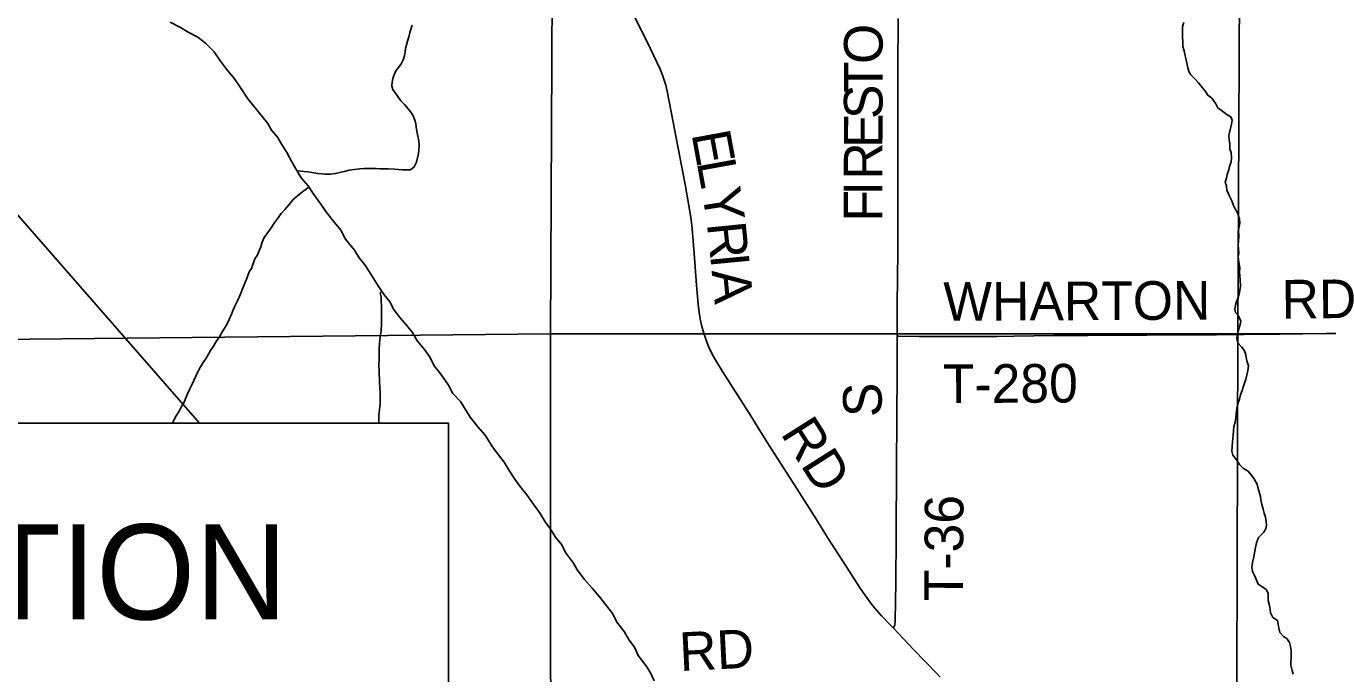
# Model space of a CAD drawing. Extents: x 0 to 34, y 0 to 22.
# Drawn here: x 4.701 to 6.615, y 18.929 to 19.882 of the extents above; entities that cross this region are included whole.
import ezdxf

# ---------------------------------------------------------------- set-up
doc = ezdxf.new("R2010")
doc.units = 0
for name, color, linetype in [('GM_X_County_Road', 7, 'Continuous'), ('GM_X_County_Road_Text', 7, 'Continuous'), ('GM_X_Minor_River', 7, 'Continuous'), ('GM_X_Rail_Line', 7, 'Continuous'), ('GM_X_Section', 7, 'Continuous'), ('GM_X_Township_Road', 7, 'Continuous'), ('GM_X_Township_Road_Text', 7, 'Continuous'), ('SH_Text', 7, 'Continuous')]:
    doc.layers.add(name, color=color, linetype=linetype)

msp = doc.modelspace()

# ---------------------------------------------------------------- linework, layer by layer
at = {"layer": 'GM_X_County_Road'}
for points in [[(5.976, 18.9964), (5.9715, 19.0011), (5.9588, 19.0146), (5.9483, 19.0263), (5.9426, 19.0337), (5.9351, 19.0437), (5.9263, 19.0565), (5.9061, 19.0879), (5.8794, 19.1298), (5.8629, 19.1562), (5.8346, 19.2008), (5.8113, 19.2375), (5.7944, 19.2636), (5.7812, 19.2847), (5.7663, 19.3084), (5.7247, 19.3739), (5.7164, 19.3873), (5.7103, 19.3982), (5.7049, 19.4093), (5.7013, 19.4182), (5.6973, 19.4299), (5.694, 19.4419), (5.6919, 19.451), (5.6905, 19.4603), (5.6889, 19.4727), (5.6866, 19.5006), (5.6831, 19.547), (5.6801, 19.584), (5.6788, 19.5965), (5.676, 19.6149), (5.6699, 19.6485), (5.6494, 19.7553), (5.6434, 19.7858), (5.6414, 19.7948), (5.6388, 19.8035), (5.6365, 19.8095), (5.633, 19.818), (5.6186, 19.849), (5.605, 19.8769), (5.5837, 19.9184)], [(6.0449, 18.9245), (6.0402, 18.9292), (6.0056, 18.9649), (5.976, 18.9964)]]:
    msp.add_lwpolyline(points, dxfattribs=at)
at = {"layer": 'GM_X_Minor_River'}
for points in [[(4.9132, 19.8872), (4.928, 19.8793), (4.9394, 19.8728), (4.9538, 19.8653), (4.9648, 19.8566), (4.9778, 19.8437), (4.9869, 19.8301), (4.9957, 19.8184), (5.0075, 19.804), (5.017, 19.7904), (5.0273, 19.7748), (5.0379, 19.7616), (5.0482, 19.7487), (5.0566, 19.7385), (5.0619, 19.7283), (5.0707, 19.718), (5.0771, 19.7074), (5.0844, 19.6957), (5.0916, 19.682), (5.0977, 19.6718), (5.1057, 19.6586), (5.116, 19.6468), (5.124, 19.634), (5.1343, 19.6199), (5.1434, 19.6071), (5.1545, 19.5927), (5.164, 19.5817), (5.1709, 19.5681), (5.1838, 19.5522), (5.1907, 19.5408), (5.199, 19.5306), (5.2089, 19.5154), (5.2185, 19.4999), (5.2276, 19.4863), (5.2364, 19.4757), (5.2413, 19.4654), (5.2509, 19.4526), (5.2604, 19.442), (5.2687, 19.4314), (5.2764, 19.4185), (5.287, 19.406), (5.295, 19.3943), (5.3011, 19.3818), (5.311, 19.3696), (5.3221, 19.3537), (5.3286, 19.3412), (5.3396, 19.3295), (5.3537, 19.3064), (5.3651, 19.2924), (5.3761, 19.2799), (5.386, 19.2644), (5.3937, 19.2534), (5.4039, 19.2405), (5.412, 19.2265), (5.4184, 19.2167), (5.4268, 19.2049), (5.4371, 19.1924), (5.4458, 19.1807), (5.4569, 19.1648), (5.4641, 19.1527), (5.4721, 19.1421), (5.4794, 19.1299), (5.4885, 19.119), (5.4939, 19.1076), (5.506, 19.0921), (5.5114, 19.0822), (5.522, 19.0678), (5.5334, 19.055), (5.5445, 19.0417), (5.5548, 19.0285), (5.5635, 19.0175), (5.5696, 19.005), (5.5803, 18.9914), (5.5875, 18.9789), (5.5955, 18.9682), (5.6009, 18.9561), (5.6134, 18.9395), (5.6195, 18.9296), (5.6245, 18.919)], [(6.4439, 19.7757), (6.4382, 19.7799), (6.4348, 19.7852), (6.4283, 19.7932), (6.4244, 19.7982), (6.4195, 19.8035), (6.4133, 19.81), (6.4103, 19.8149), (6.4087, 19.8203), (6.4072, 19.8275), (6.406, 19.8336), (6.4045, 19.8404), (6.4033, 19.8454), (6.4014, 19.8514), (6.4014, 19.8568), (6.401, 19.867), (6.4009, 19.8811), (6.4028, 19.8868)], [(5.0997, 19.6685), (5.1153, 19.6674), (5.124, 19.6659), (5.1298, 19.6648), (5.1401, 19.664), (5.1485, 19.6636), (5.1561, 19.6648), (5.1641, 19.667), (5.1691, 19.6678), (5.1763, 19.6697), (5.1836, 19.6708), (5.1916, 19.6716), (5.1981, 19.6723), (5.2076, 19.6723), (5.216, 19.672), (5.221, 19.6719), (5.2282, 19.6716), (5.2336, 19.6716), (5.2431, 19.6712), (5.2481, 19.6708), (5.2542, 19.6704), (5.2664, 19.6704), (5.2717, 19.6746), (5.2751, 19.6814), (5.2766, 19.6879), (5.2778, 19.694), (5.2785, 19.6993), (5.2789, 19.7061), (5.2785, 19.713), (5.2769, 19.7198), (5.2754, 19.7271), (5.2746, 19.7331), (5.2739, 19.7381), (5.2727, 19.7434), (5.27, 19.7495), (5.2666, 19.7548), (5.2627, 19.7601), (5.2574, 19.7662), (5.252, 19.7719), (5.2478, 19.778), (5.244, 19.783), (5.2401, 19.7883), (5.2386, 19.7936), (5.2394, 19.7989), (5.2405, 19.8043), (5.2424, 19.81), (5.2447, 19.8157), (5.2485, 19.8206), (5.2526, 19.8263), (5.2553, 19.832), (5.2572, 19.8385), (5.2583, 19.8438), (5.2587, 19.8491), (5.2602, 19.8541), (5.2617, 19.8594), (5.2636, 19.8659), (5.2651, 19.8723), (5.2689, 19.883)], [(6.5244, 19.1479), (6.524, 19.1528), (6.5229, 19.1593), (6.521, 19.1654), (6.5194, 19.1711), (6.5175, 19.1783), (6.5163, 19.1848), (6.5156, 19.1901), (6.5136, 19.1969), (6.5117, 19.203), (6.5106, 19.208), (6.506, 19.2163), (6.5017, 19.222), (6.4975, 19.2274), (6.4907, 19.2312), (6.4849, 19.2369), (6.4803, 19.2437), (6.475, 19.2506), (6.4734, 19.2567), (6.4738, 19.2635), (6.4745, 19.2703), (6.4753, 19.2802), (6.476, 19.2867), (6.4764, 19.2924), (6.4787, 19.3011), (6.4794, 19.3065), (6.4805, 19.3164), (6.4813, 19.3221), (6.4828, 19.3274), (6.4847, 19.3331), (6.4862, 19.3392), (6.4885, 19.3456), (6.49, 19.3506), (6.4923, 19.3567), (6.4942, 19.3624), (6.4957, 19.3684), (6.4972, 19.3753), (6.4979, 19.3818), (6.4956, 19.3894), (6.4948, 19.3947), (6.4937, 19.4), (6.4918, 19.405), (6.4876, 19.4099), (6.4822, 19.416), (6.481, 19.4221), (6.4822, 19.4316), (6.486, 19.443), (6.4867, 19.4479), (6.4833, 19.4555), (6.4787, 19.4605), (6.4779, 19.4654), (6.479, 19.4711), (6.4805, 19.4768), (6.4828, 19.4825), (6.4843, 19.4879), (6.4851, 19.4928), (6.4862, 19.4993), (6.4858, 19.5084), (6.4854, 19.5141), (6.485, 19.5206), (6.4854, 19.5259), (6.4842, 19.532), (6.4834, 19.5373), (6.483, 19.5426), (6.4838, 19.5476), (6.4834, 19.5536), (6.4826, 19.5601), (6.4834, 19.565), (6.4837, 19.5727), (6.4833, 19.581), (6.4841, 19.5871), (6.4852, 19.5924), (6.4848, 19.5977), (6.4817, 19.6069), (6.4783, 19.613), (6.476, 19.6179), (6.4737, 19.6244), (6.4699, 19.6316), (6.466, 19.6404), (6.4656, 19.6468), (6.4637, 19.6521), (6.4656, 19.6582), (6.4667, 19.6632), (6.469, 19.6704), (6.4701, 19.6753), (6.4724, 19.6818), (6.4732, 19.6879), (6.4724, 19.6955), (6.4708, 19.7004), (6.4704, 19.7084), (6.4697, 19.7149), (6.4693, 19.7206), (6.4708, 19.727), (6.473, 19.7373), (6.4738, 19.743), (6.4719, 19.748), (6.4661, 19.7518), (6.4581, 19.7575), (6.4531, 19.7613), (6.4501, 19.7674), (6.4439, 19.7757)], [(5.1171, 19.645), (5.1092, 19.6393), (5.1005, 19.6325), (5.0932, 19.626), (5.0879, 19.6192), (5.0814, 19.6119), (5.0761, 19.6059), (5.07, 19.5979), (5.0658, 19.5918), (5.0624, 19.5865), (5.059, 19.5815), (5.0552, 19.5762), (5.051, 19.5709), (5.048, 19.5641), (5.0461, 19.5568), (5.0407, 19.5443), (5.0373, 19.5393), (5.0324, 19.5253), (5.029, 19.52), (5.0259, 19.512), (5.0229, 19.5036), (5.0191, 19.4952), (5.0157, 19.4865), (5.0123, 19.4785), (5.0092, 19.4717), (5.0062, 19.4652), (5.0032, 19.458), (4.9998, 19.45), (4.9956, 19.442), (4.9906, 19.4337), (4.9853, 19.4249), (4.9808, 19.4177), (4.9766, 19.4108), (4.9724, 19.4044), (4.9694, 19.3994), (4.9659, 19.3934), (4.9617, 19.3869), (4.9572, 19.3797), (4.953, 19.3721), (4.9454, 19.3553), (4.9412, 19.3474), (4.9382, 19.3409), (4.9348, 19.3325), (4.9329, 19.3276), (4.9298, 19.3223), (4.926, 19.3154), (4.9219, 19.3086), (4.9184, 19.3021), (4.9162, 19.2976)], [(5.224, 19.4917), (5.2218, 19.4894), (5.2229, 19.4833), (5.2233, 19.4776), (5.2237, 19.4696), (5.2238, 19.4491), (5.2234, 19.4438), (5.2231, 19.4335), (5.2219, 19.4271), (5.2212, 19.4206), (5.2208, 19.4141), (5.2204, 19.4073), (5.2201, 19.3997), (5.2201, 19.3921), (5.2197, 19.3833), (5.2201, 19.3742), (5.2209, 19.3582), (5.2213, 19.3506), (5.2217, 19.3423), (5.2218, 19.3343), (5.2214, 19.3263), (5.2207, 19.3175), (5.2199, 19.3096), (5.2199, 19.3016), (5.2197, 19.2976)], [(6.5639, 18.9288), (6.562, 18.9341), (6.5604, 18.9417), (6.5604, 18.9467), (6.5608, 18.9524), (6.5608, 18.9573), (6.5608, 18.9634), (6.56, 18.9695), (6.5584, 18.9752), (6.5542, 18.9813), (6.5493, 18.984), (6.5443, 18.9901), (6.5424, 18.9961), (6.5416, 19.0022), (6.5408, 19.0075), (6.5339, 19.0121), (6.5305, 19.019), (6.5297, 19.0239), (6.5289, 19.0296), (6.527, 19.0368), (6.527, 19.0425), (6.527, 19.0479), (6.5239, 19.0532), (6.5174, 19.0578), (6.5121, 19.0608), (6.5101, 19.0657), (6.5074, 19.073), (6.504, 19.0798), (6.5028, 19.0859), (6.504, 19.0931), (6.5059, 19.1011), (6.5074, 19.1095), (6.5085, 19.1148), (6.5096, 19.1216), (6.5127, 19.1296), (6.5199, 19.1368), (6.5233, 19.1425), (6.5244, 19.1479)]]:
    msp.add_lwpolyline(points, dxfattribs=at)
at = {"layer": 'GM_X_Rail_Line'}
msp.add_lwpolyline([(2.7155, 20.9), (2.73, 20.8809), (3.0413, 20.4799), (3.1308, 20.3674), (3.1683, 20.3431), (3.6096, 20.1154), (3.6962, 20.0743), (3.8747, 20.0142), (4.4727, 19.7986), (4.5351, 19.7653), (4.5741, 19.7323), (4.625, 19.6768), (4.956, 19.2976)], dxfattribs=at)
at = {"layer": 'GM_X_Section'}
for points in [[(5.4771, 20.4356), (6.4874, 20.4413), (6.4824, 19.4291), (5.472, 19.4291)], [(6.4874, 20.4413), (7.5127, 20.4367), (7.5091, 19.4296), (6.4824, 19.4291)], [(4.4682, 20.4307), (5.4771, 20.4356), (5.472, 19.4291), (4.4662, 19.4189)], [(4.4724, 18.5805), (4.4738, 18.4018), (5.4223, 18.414), (5.4724, 18.4134), (5.472, 19.4291), (4.4662, 19.4189), (4.4671, 19.2976), (5.3223, 19.2976), (5.3223, 18.5805)], [(5.472, 19.4291), (6.4824, 19.4291), (6.4793, 18.4161), (5.4724, 18.4134)], [(6.4824, 19.4291), (7.5091, 19.4296), (7.4947, 18.4172), (6.4793, 18.4161)]]:
    msp.add_lwpolyline(points, close=True, dxfattribs=at)
at = {"layer": 'GM_X_Township_Road'}
for points in [[(5.9816, 19.4255), (5.9816, 19.4421), (5.9818, 19.467), (5.9822, 19.5165), (5.9826, 19.5446), (5.9825, 19.5802), (5.9824, 19.5974), (5.9824, 19.6126), (5.9826, 19.6347), (5.9824, 19.6595), (5.9825, 19.6936), (5.9826, 19.7061), (5.9827, 19.7589), (5.9827, 19.79), (5.9827, 19.8366), (5.9831, 19.8738), (5.983, 19.8925)], [(5.976, 18.9964), (5.9764, 18.9972), (5.9773, 18.9989), (5.978, 19.0008), (5.9784, 19.003), (5.9787, 19.005), (5.9792, 19.0373), (5.9795, 19.0608), (5.9797, 19.0838), (5.98, 19.111), (5.9802, 19.1257), (5.9802, 19.1506), (5.9808, 19.216), (5.9808, 19.2339), (5.9807, 19.2591), (5.9809, 19.2797), (5.981, 19.2965), (5.9812, 19.3126), (5.9813, 19.3271), (5.9815, 19.352), (5.9816, 19.3677), (5.9817, 19.3829), (5.9818, 19.408), (5.9816, 19.4205), (5.9816, 19.4255)], [(5.9816, 19.4255), (5.9839, 19.4255), (6.0136, 19.4254), (6.0477, 19.425), (6.1035, 19.4251), (6.1284, 19.4254), (6.1532, 19.4258), (6.2119, 19.4265), (6.2618, 19.4268), (6.3176, 19.4271), (6.3485, 19.4272), (6.4014, 19.4275), (6.42, 19.4275), (6.4509, 19.4276), (6.4695, 19.428), (6.4912, 19.4283), (6.5158, 19.4286), (6.544, 19.4287), (6.6122, 19.4295), (6.6463, 19.4298)]]:
    msp.add_lwpolyline(points, dxfattribs=at)
at = {"layer": 'SH_Text'}
msp.add_lwpolyline([(3.1024, 19.2976), (5.3223, 19.2976), (5.3223, 18.5805), (3.1024, 18.5805)], close=True, dxfattribs=at)

# ---------------------------------------------------------------- texts
at = {"layer": 'GM_X_County_Road_Text'}
for s, height, rotation, p in [('E', 0.0568, 280.4287, (5.6791, 19.7232)), ('L', 0.0568, 280.361, (5.6867, 19.6815)), ('Y', 0.0568, 278.8413, (5.6943, 19.64)), ('R', 0.0568, 275.7883, (5.7019, 19.5914)), ('I', 0.0568, 275.4842, (5.7066, 19.5451)), ('A', 0.0568, 275.4725, (5.7088, 19.5219)), ('RD', 0.05682, 302.4671, (5.8093, 19.2827))]:
    msp.add_text(s, height=height, rotation=rotation, dxfattribs=at).set_placement(p)
at = {"layer": 'GM_X_Township_Road_Text'}
for s, height, rotation, p in [('O', 0.0568, 89.8713, (5.9602, 19.8258)), ('T', 0.0568, 89.8693, (5.9601, 19.7832)), ('S', 0.0568, 89.8719, (5.9601, 19.7449)), ('E', 0.0568, 89.8693, (5.96, 19.7024)), ('R', 0.0568, 89.8718, (5.9599, 19.6557)), ('F', 0.0568, 89.8693, (5.9597, 19.5941)), ('I', 0.0568, 89.8721, (5.9598, 19.6324)), ('WHARTON', 0.05682, 0.2681, (6.0495, 19.4482)), ('RD', 0.05682, 0.4936, (6.5469, 19.4515)), ('T-280', 0.05682, 0.2811, (6.0488, 19.3272)), ('S', 0.0568, 90, (5.9589, 19.3067)), ('T-36', 0.05682, 89.6458, (6.0782, 19.0358)), ('RD', 0.05682, 2.8123, (5.6627, 18.9332))]:
    msp.add_text(s, height=height, rotation=rotation, dxfattribs=at).set_placement(p)
at = {"layer": 'SH_Text'}
msp.add_text('BEGIN ACQUISTION', height=0.14, dxfattribs=at).set_placement((3.2855, 19.0091))

doc.saveas('drawing.dxf')
